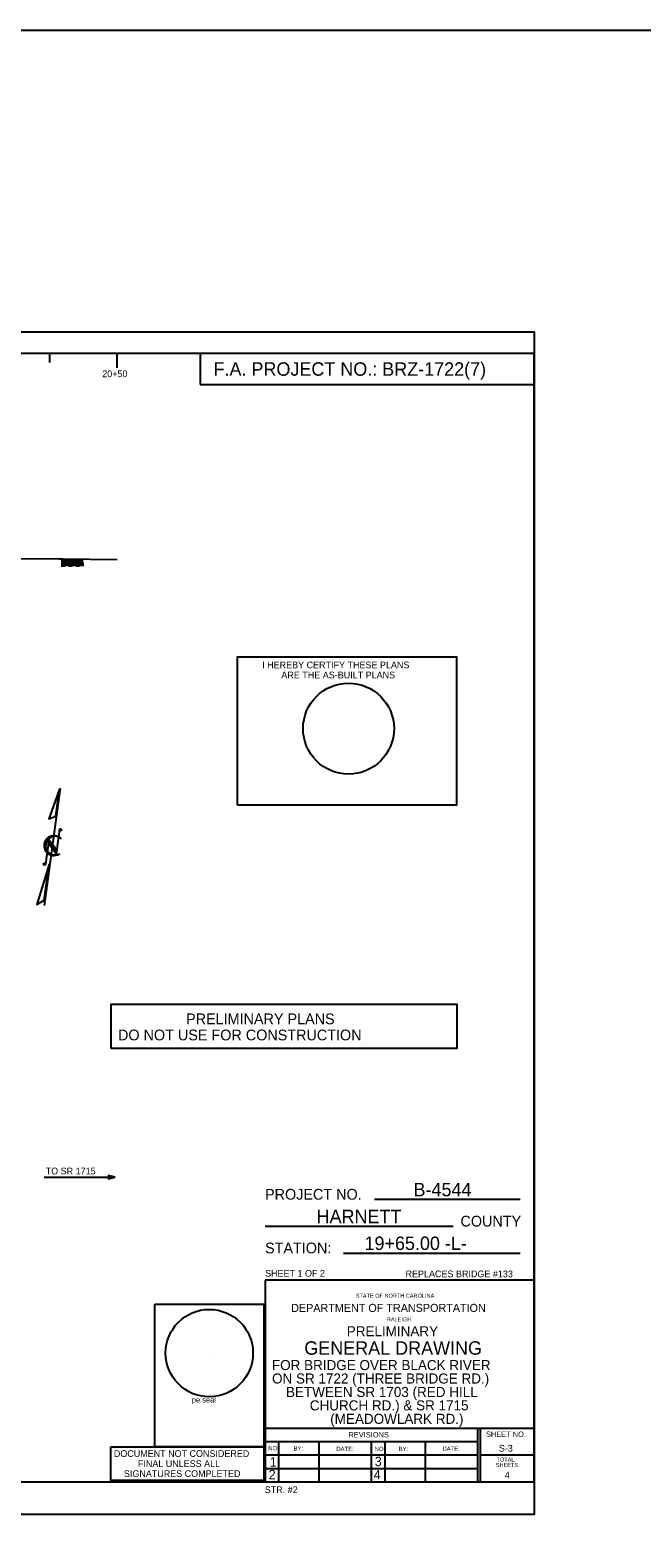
# Model space of a CAD drawing. Extents: x 471 to 2034, y -623 to 126.
# Drawn here: x 1659.1 to 1750.2, y -98.6 to 125.8 of the extents above; entities that cross this region are included whole.
import ezdxf

# ---------------------------------------------------------------- set-up
doc = ezdxf.new("R2010")
doc.units = 0
for name, color, linetype in [('Arrowhead Terminators CELL', 7, 'Continuous'), ('Dimension Lines', 7, 'Continuous'), ('Mis Existing Ground Lines', 7, 'Continuous'), ('Miscellaneous Lines CELL', 7, 'Continuous'), ('Plan Sheet CELL', 7, 'Continuous'), ('Plot Shape CELL', 7, 'Continuous'), ('Sheet North Arrow CELL', 7, 'Continuous'), ('Sheet Sticker Exception Certification CELL', 7, 'Continuous'), ('Subtitle Text', 7, 'Continuous'), ('Text', 7, 'Continuous'), ('Title Text', 7, 'Continuous'), ('User Information Notes', 7, 'Continuous'), ('User Information Notes CELL', 7, 'Continuous')]:
    doc.layers.add(name, color=color, linetype=linetype)

msp = doc.modelspace()

# ---------------------------------------------------------------- linework, layer by layer
at = {"layer": 'Arrowhead Terminators CELL'}
msp.add_lwpolyline([(1671.79, -44.97), (1670.79, -44.72), (1670.79, -45.22)], close=True, dxfattribs=at)
at = {"layer": 'Dimension Lines'}
for p, q in [((1662.08, 76.3), (1662.08, 77.7)), ((1672.08, 75.49), (1672.08, 77.7)), ((1661.22, -44.97), (1671.79, -44.97))]:
    msp.add_line(p, q, dxfattribs=at)
at = {"layer": 'Mis Existing Ground Lines'}
msp.add_lwpolyline([(1642.83, 47.23), (1663.44, 47.09), (1664.01, 47.08), (1672.08, 46.99)], dxfattribs=at)
at = {"layer": 'Miscellaneous Lines CELL'}
for p, q in [((1663.78, 46.47), (1664.31, 46.46)), ((1663.78, 46.26), (1664.3, 46.25)), ((1663.78, 46.05), (1664.3, 46.04)), ((1663.85, 47.03), (1663.84, 46.51)), ((1664.06, 47.03), (1664.05, 46.51)), ((1664.27, 47.03), (1664.26, 46.51)), ((1664.31, 46.98), (1664.84, 46.97)), ((1664.31, 46.77), (1664.83, 46.76)), ((1664.31, 46.56), (1664.83, 46.55)), ((1664.36, 46.51), (1664.35, 45.99)), ((1664.57, 46.51), (1664.56, 45.98)), ((1664.78, 46.5), (1664.77, 45.98)), ((1664.88, 46.48), (1665.41, 46.47)), ((1664.88, 46.27), (1665.4, 46.26)), ((1664.88, 46.06), (1665.4, 46.05)), ((1664.95, 47.05), (1664.94, 46.53)), ((1665.16, 47.04), (1665.15, 46.52)), ((1665.37, 47.04), (1665.36, 46.52)), ((1665.41, 46.99), (1665.94, 46.98)), ((1665.41, 46.78), (1665.93, 46.77)), ((1665.41, 46.57), (1665.93, 46.57)), ((1665.46, 46.52), (1665.45, 46)), ((1665.67, 46.52), (1665.66, 46)), ((1665.88, 46.51), (1665.87, 45.99)), ((1665.97, 46.05), (1666.49, 46.05)), ((1665.98, 46.47), (1666.5, 46.46)), ((1665.98, 46.26), (1666.5, 46.25)), ((1666.05, 47.04), (1666.04, 46.52)), ((1666.25, 47.04), (1666.24, 46.52)), ((1666.46, 47.03), (1666.45, 46.51)), ((1666.5, 46.57), (1667.02, 46.56)), ((1666.51, 46.98), (1667.03, 46.97)), ((1666.51, 46.77), (1667.03, 46.77)), ((1666.55, 46.51), (1666.54, 45.99)), ((1666.76, 46.51), (1666.75, 45.99)), ((1666.97, 46.51), (1666.96, 45.99))]:
    msp.add_line(p, q, dxfattribs=at)
at = {"layer": 'Plan Sheet CELL'}
for p, q in [((1734.18, 80.85), (1734.18, 80.85)), ((1478.11, 77.7), (1734.11, 77.7)), ((1684.46, 77.59), (1684.46, 73.03)), ((1734.11, 77.7), (1734.11, -90.3)), ((1684.46, 73.03), (1734.11, 73.03)), ((1732.11, -48.3), (1710.38, -48.3)), ((1722.11, -52.3), (1694.11, -52.3)), ((1732.11, -56.29), (1705.8, -56.29)), ((1734.11, -60.3), (1694.11, -60.3)), ((1694.11, -60.3), (1694.11, -90.3)), ((1694.11, -82.3), (1734.11, -82.3)), ((1725.71, -82.3), (1725.71, -90.3)), ((1726.11, -82.3), (1726.11, -90.3)), ((1694.11, -84.29), (1725.73, -84.29)), ((1694.14, -84.29), (1694.14, -90.3)), ((1696.11, -84.29), (1696.11, -90.3)), ((1702.11, -84.33), (1702.11, -90.33)), ((1709.92, -84.29), (1709.92, -90.35)), ((1711.92, -84.29), (1711.92, -90.3)), ((1717.92, -84.29), (1717.92, -90.3)), ((1694.11, -86.3), (1725.79, -86.3)), ((1726.11, -86.3), (1734.04, -86.3)), ((1694.11, -88.3), (1725.73, -88.3)), ((1478.11, -90.3), (1734.11, -90.3)), ((1734.18, -95.15), (1734.18, -95.15))]:
    msp.add_line(p, q, dxfattribs=at)
for points in [[(1689.94, 10.46), (1722.67, 10.46), (1722.67, 32.46), (1689.94, 32.46)], [(1671.21, -25.8), (1671.21, -19.22), (1722.67, -19.22), (1722.67, -25.8)]]:
    msp.add_lwpolyline(points, close=True, dxfattribs=at)
at = {"layer": 'Plot Shape CELL'}
msp.add_lwpolyline([(1469.68, 80.85), (1734.18, 80.85), (1734.18, -95.15), (1469.68, -95.15)], close=True, dxfattribs=at)
at = {"layer": 'Sheet North Arrow CELL'}
for p, q in [((1661.28, -4.51), (1663.67, 12.93)), ((1663.49, 6.77), (1663.01, 3.19)), ((1661.93, 5.27), (1661.43, 1.63)), ((1663.01, 3.19), (1661.85, 4.71)), ((1661.91, 5.14), (1661.87, 4.81)), ((1663.02, 3.29), (1661.87, 4.81)), ((1661.87, 4.81), (1663.02, 3.29)), ((1663.06, 3.62), (1661.91, 5.14)), ((1663.08, 3.75), (1661.93, 5.27)), ((1663.81, 5.37), (1663.82, 5.36)), ((1663.02, 3.29), (1663.06, 3.62))]:
    msp.add_line(p, q, dxfattribs=at)
for points in [[(1663.52, 12.8), (1661.91, 8.4), (1662.97, 8.77)], [(1661.98, 1.65), (1660.15, -4.36), (1661.25, -3.71)]]:
    msp.add_lwpolyline(points, close=True, dxfattribs=at)
for centre in [(1663.64, 6.75), (1661.29, 1.64)]:
    msp.add_circle(centre, 0.144, dxfattribs=at)
for centre, radius, start, end in [((1662.69, 4.4), 1.48, 40.0635, 304.6175), ((1662.83, 4.39), 1.39, 45.3185, 300.8522)]:
    msp.add_arc(centre, radius, start, end, dxfattribs=at)
at = {"layer": 'Sheet Sticker Exception Certification CELL'}
msp.add_lwpolyline([(1671.13, -85.08), (1693.92, -85.08), (1693.92, -90.1), (1671.13, -90.1)], close=True, dxfattribs=at)
at = {"layer": 'User Information Notes'}
msp.add_line((1722.67, 10.46), (1722.67, 10.46), dxfattribs=at)
msp.add_lwpolyline([(1359.3, 125.77), (2033.54, 125.77), (2033.54, -623.41), (1359.3, -623.41)], close=True, dxfattribs=at)
msp.add_circle((1706.54, 21.81), 6.77, dxfattribs=at)
at = {"layer": 'User Information Notes CELL'}
msp.add_line((1685.81, -71.14), (1685.81, -71.14), dxfattribs=at)
msp.add_lwpolyline([(1677.71, -63.84), (1693.92, -63.84), (1693.92, -85.08), (1677.71, -85.08)], close=True, dxfattribs=at)
msp.add_circle((1685.81, -71.14), 6.5, dxfattribs=at)

# ---------------------------------------------------------------- texts
at = {"layer": 'Dimension Lines'}
msp.add_text('STR. #2', height=1, dxfattribs=at).set_placement((1694.07, -91.98))
at = {"layer": 'Plan Sheet CELL'}
for s, height, p in [('PRELIMINARY PLANS', 1.6, (1682.35, -22.19)), ('DO NOT USE FOR CONSTRUCTION', 1.6, (1672.22, -24.59)), ('PROJECT NO.', 1.6, (1694.11, -48.3)), ('COUNTY', 1.6, (1723.2, -52.3)), ('STATION:', 1.6, (1694.11, -56.29)), ('SHEET 1 OF 2', 1, (1694.11, -59.76)), ('STATE OF NORTH CAROLINA', 0.6, (1707.61, -62.9)), ('DEPARTMENT OF TRANSPORTATION', 1.2, (1697.99, -65.01)), ('RALEIGH', 0.6, (1712.23, -66.41)), ('REVISIONS', 0.8, (1706.53, -83.69)), ('SHEET NO.', 0.8, (1726.99, -83.61)), ('NO.', 0.637, (1694.59, -85.61)), ('BY:', 0.637, (1698.36, -85.64)), ('DATE:', 0.637, (1704.72, -85.71)), ('NO.', 0.637, (1710.43, -85.71)), ('BY:', 0.637, (1714, -85.72)), ('DATE:', 0.637, (1720.52, -85.68)), ('1', 1.4, (1694.8, -88.03)), ('3', 1.4, (1710.44, -87.96)), ('SHEETS', 0.6, (1728.47, -88.09)), ('TOTAL', 0.6, (1728.56, -87.28)), ('2', 1.4, (1694.65, -89.93)), ('4', 1.4, (1710.29, -89.93))]:
    msp.add_text(s, height=height, dxfattribs=at).set_placement(p)
at = {"layer": 'Sheet Sticker Exception Certification CELL'}
for s, p in [('DOCUMENT NOT CONSIDERED', (1671.6, -86.59)), ('FINAL UNLESS ALL', (1675.18, -88.09)), ('SIGNATURES COMPLETED', (1673.1, -89.58))]:
    msp.add_text(s, height=0.9978, dxfattribs=at).set_placement(p)
at = {"layer": 'Subtitle Text'}
for s, p in [('PRELIMINARY', (1706.27, -68.63)), ('FOR BRIDGE OVER BLACK RIVER', (1695.13, -73.67)), ('ON SR 1722 (THREE BRIDGE RD.)', (1695.15, -75.67)), ('BETWEEN SR 1703 (RED HILL', (1697.23, -77.67)), ('CHURCH RD.) & SR 1715', (1700.77, -79.67)), ('(MEADOWLARK RD.)', (1703.81, -81.67))]:
    msp.add_text(s, height=1.5, dxfattribs=at).set_placement(p)
at = {"layer": 'Text'}
for s, p in [('20+50', (1669.87, 74.12)), ('I HEREBY CERTIFY THESE PLANS', (1693.68, 30.79)), ('ARE THE AS-BUILT PLANS', (1696.53, 29.29)), ('TO SR 1715', (1661.45, -44.54)), ('REPLACES BRIDGE #133', (1715.02, -59.85)), ('S-3', (1728.91, -85.8)), ('4', (1729.79, -89.8))]:
    msp.add_text(s, height=1, dxfattribs=at).set_placement(p)
at = {"layer": 'Title Text'}
for s, p in [('F.A. PROJECT NO.: BRZ-1722(7)', (1686.44, 74.33)), ('B-4544', (1716.21, -47.8)), ('HARNETT', (1701.78, -51.8)), ('19+65.00 -L-', (1708.91, -55.79)), ('GENERAL DRAWING', (1699.95, -71.38))]:
    msp.add_text(s, height=2, dxfattribs=at).set_placement(p)
at = {"layer": 'User Information Notes CELL'}
msp.add_text('pe seal', height=0.8, dxfattribs=at).set_placement((1683.22, -78.49))

doc.saveas('drawing.dxf')
